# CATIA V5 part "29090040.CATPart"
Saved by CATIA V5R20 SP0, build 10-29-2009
Part number: 29090040
Definition: NONE
Nomenclature: 29090040
Source: Unknown
Description: 29090040
Bounding box of the stored display mesh (mm): x -20 to 44.548, y -59 to 93.548, z -49 to 49
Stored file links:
  C:\Users\Utente\Desktop\IO LAVORO\3D X SITO CF\X SITO\PLASTICA\RF1\29090040.CATPart
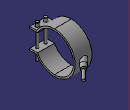
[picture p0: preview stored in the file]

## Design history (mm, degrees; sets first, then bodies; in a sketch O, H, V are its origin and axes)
Body1 "29090040" (main body)
  Solid1: solid without history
